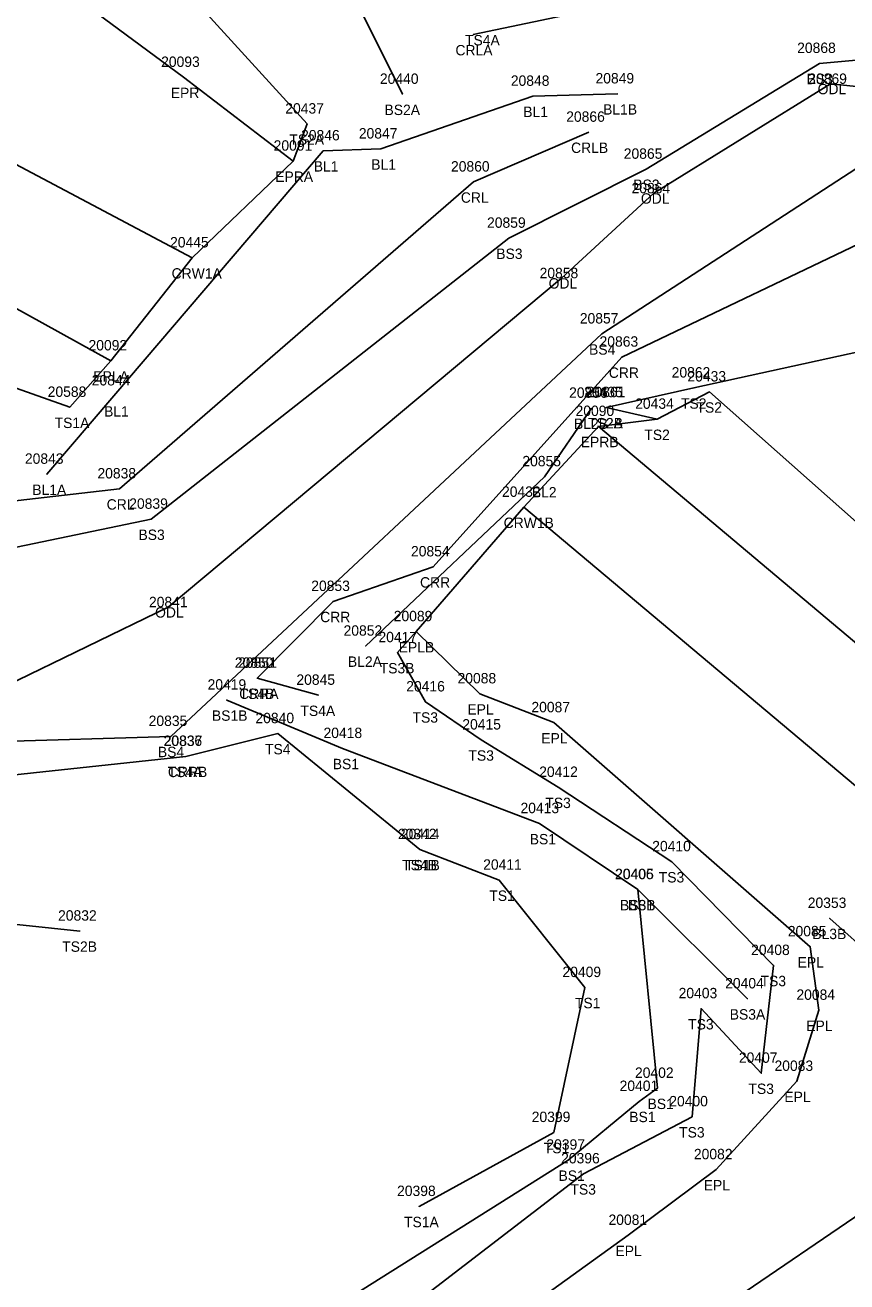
# Model space of a CAD drawing. Extents: x 1813127 to 1814107, y 1178171 to 1179078.
# Drawn here: x 1813724.7 to 1813803.8, y 1178619.3 to 1178740.3 of the extents above; entities that cross this region are included whole.
import ezdxf

# ---------------------------------------------------------------- set-up
doc = ezdxf.new("R2010")
doc.units = 0
for name, color, linetype in [('Default', 7, 'Continuous'), ('RD_DTM_BkLn1', 7, 'Continuous'), ('RD_DTM_BkLn2', 7, 'Continuous'), ('RD_EX_H2O', 7, 'Continuous'), ('RD_EX_H2O_txCode', 7, 'Continuous'), ('RD_EX_Road', 7, 'Continuous'), ('RD_EX_Road_txCode', 7, 'Continuous'), ('RD_SMD_Locator', 7, 'Continuous'), ('RD_SMD_Misc', 7, 'Continuous')]:
    doc.layers.add(name, color=color, linetype=linetype)

msp = doc.modelspace()

# ---------------------------------------------------------------- linework, layer by layer
at = {"layer": 'Default'}
msp.add_lwpolyline([(1813785.53, 1178702.33), (1813779.87, 1178701.64), (1813772.7, 1178693.86), (1813762.33, 1178681.89), (1813760.53, 1178679.87)], dxfattribs=at)
at = {"layer": 'RD_DTM_BkLn1'}
msp.add_line((1813820.26, 1178638.1), (1813802.14, 1178654.3), dxfattribs=at)
for points in [[(1813740.76, 1178717.86), (1813693.97, 1178742.65), (1813652.18, 1178753.85), (1813643.74, 1178755.64), (1813595, 1178763.51), (1813546.44, 1178770.61), (1813497.6, 1178777.62), (1813448.59, 1178785.89), (1813401.09, 1178795.04), (1813353.48, 1178806.76), (1813306.05, 1178819.85), (1813260.03, 1178834.12), (1813213.64, 1178849.47), (1813166.61, 1178866.29)], [(1813726.79, 1178697.04), (1813733.22, 1178704.58), (1813753.39, 1178728.16), (1813758.93, 1178728.34), (1813773.56, 1178733.41), (1813781.71, 1178733.64)], [(1813757.46, 1178680.5), (1813774.67, 1178696.8), (1813779.19, 1178703.39)], [(1814069.63, 1178419.56), (1814043.03, 1178443.95), (1814031.76, 1178453.98), (1813994.68, 1178489.07), (1813958.14, 1178523.5), (1813920.87, 1178558.86), (1813884.46, 1178593.47), (1813847.15, 1178628.98), (1813831.28, 1178643.33), (1813810.03, 1178662.5), (1813772.7, 1178693.86)], [(1813831.28, 1178643.33), (1813821.11, 1178637.41), (1813809.78, 1178629.12), (1813788.78, 1178614.79), (1813747.67, 1178586.85), (1813706.5, 1178558.14), (1813665.11, 1178528), (1813623.37, 1178496.83), (1813582.75, 1178466.66)]]:
    msp.add_lwpolyline(points, dxfattribs=at)
at = {"layer": 'RD_DTM_BkLn2'}
for p, q in [((1813752.92, 1178675.77), (1813747.03, 1178677.41)), ((1813794.23, 1178646.56), (1813783.65, 1178657.07))]:
    msp.add_line(p, q, dxfattribs=at)
for points in [[(1813751.85, 1178730.74), (1813741.17, 1178742.44), (1813717.67, 1178762.1), (1813698.84, 1178775.48), (1813689.15, 1178782.4), (1813688.55, 1178790.23), (1813686.56, 1178796.15), (1813687.57, 1178849.05), (1813684.25, 1178850.31), (1813686.08, 1178900.25), (1813688.49, 1178947.42), (1813691.04, 1178995.37), (1813694.64, 1179045.56)], [(1813761, 1178733.6), (1813755.04, 1178745.59), (1813738.22, 1178758.92), (1813720.3, 1178769.51), (1813690.62, 1178785.84)], [(1813728.98, 1178703.48), (1813680.74, 1178720.54), (1813670.9, 1178725.8), (1813665.35, 1178733.78), (1813654.36, 1178734.63), (1813647.32, 1178729.73), (1813639.1, 1178730.74), (1813591.11, 1178743.16), (1813543.28, 1178751.57), (1813511.7, 1178756.57), (1813494.92, 1178760.32), (1813445.74, 1178769.42), (1813422.91, 1178772.94), (1813422.78, 1178770.34)], [(1813501.61, 1178700.78), (1813535.62, 1178707.92), (1813578.65, 1178686.08), (1813588.2, 1178681.74), (1813622.61, 1178682.2), (1813653.79, 1178685.74), (1813685.17, 1178685.29), (1813723.1, 1178689.85), (1813736.83, 1178692.71), (1813771.26, 1178719.75), (1813784.46, 1178726.39), (1813801.14, 1178736.57), (1813819.08, 1178738.18), (1813840.25, 1178734.78), (1813848.44, 1178735.38), (1813862.15, 1178734.12), (1813885.61, 1178732.56), (1813903.34, 1178733.15)], [(1813751.85, 1178730.74), (1813750.48, 1178727.17), (1813740.76, 1178717.86)], [(1813494.55, 1178680.43), (1813533.86, 1178695.27), (1813573.03, 1178675.94), (1813630.33, 1178669.28), (1813656.92, 1178672.11), (1813691.39, 1178675.03), (1813721.31, 1178671.27), (1813738.7, 1178671.81), (1813780.2, 1178710.54), (1813805.93, 1178727.26), (1813819.91, 1178727.35), (1813841.4, 1178723.71), (1813860.66, 1178719.9), (1813869.89, 1178724.9), (1813872.35, 1178725.71), (1813884.47, 1178724.42), (1813903.61, 1178724.04)], [(1813740.76, 1178717.86), (1813732.94, 1178707.95), (1813728.98, 1178703.48)], [(1813780.61, 1178703.45), (1813789.06, 1178705.34), (1813820, 1178712.11), (1813829.02, 1178714.89)], [(1814080.77, 1178431.89), (1814053.55, 1178456.53), (1814053.55, 1178456.53), (1814043.11, 1178466.04), (1814008.23, 1178502.68), (1813981.17, 1178545.08), (1813940.17, 1178583.78), (1813898.27, 1178611.44), (1813860.48, 1178642.94), (1813824.26, 1178675.11), (1813790.56, 1178704.96), (1813785.53, 1178702.33), (1813780.61, 1178703.45)], [(1813648.32, 1178539.4), (1813697.26, 1178570.92), (1813738.71, 1178599.2), (1813778.43, 1178629.72), (1813788.89, 1178635.21), (1813789.75, 1178645.61), (1813795.55, 1178639.4), (1813796.73, 1178649.77), (1813786.93, 1178659.75), (1813776.01, 1178666.91), (1813768.6, 1178671.47), (1813763.23, 1178675.13), (1813760.53, 1178679.87)], [(1813647.13, 1178541.2), (1813695.54, 1178572.96), (1813738.1, 1178600.74), (1813742.95, 1178609.65), (1813776.97, 1178631.04), (1813783.78, 1178636.69), (1813785.55, 1178637.95), (1813783.65, 1178657.07), (1813774.21, 1178663.42), (1813755.25, 1178670.65), (1813744.09, 1178675.31)], [(1813740.16, 1178669.89), (1813749.02, 1178672.08), (1813762.69, 1178660.92)], [(1813623.26, 1178662.12), (1813655.04, 1178658.73), (1813668.37, 1178660.89), (1813682.02, 1178658.15), (1813729.97, 1178653.08)], [(1813762.61, 1178626.58), (1813775.57, 1178633.7), (1813778.57, 1178647.65), (1813770.33, 1178657.98), (1813762.69, 1178660.92)]]:
    msp.add_lwpolyline(points, dxfattribs=at)
at = {"layer": 'RD_EX_H2O'}
for points in [[(1813767.83, 1178739.34), (1813802.7, 1178746.65), (1813832.24, 1178749.11), (1813880.12, 1178745.59), (1813913.04, 1178737.89)], [(1813497.15, 1178691.5), (1813535.61, 1178703.5), (1813575.96, 1178680.52), (1813619.86, 1178677.62), (1813650.02, 1178676.71), (1813688.26, 1178680.15), (1813722.87, 1178676.67), (1813738.45, 1178684.24), (1813776.33, 1178715.9), (1813785.2, 1178724.07), (1813802.21, 1178734.6), (1813820.03, 1178732.78), (1813837.63, 1178729.78), (1813857.38, 1178730.32)], [(1813721.21, 1178694.19), (1813733.77, 1178695.63), (1813767.86, 1178725.16), (1813778.94, 1178729.95)], [(1813747.03, 1178677.41), (1813754.34, 1178684.8), (1813763.95, 1178688.13), (1813782.12, 1178708.31), (1813807.89, 1178720.63), (1813829.02, 1178714.89), (1813841.06, 1178713.13), (1813882.92, 1178708.73), (1813906.37, 1178716.29)], [(1813494.93, 1178677.14), (1813538.08, 1178685.02), (1813548.67, 1178684.4), (1813554.06, 1178674.83), (1813572.78, 1178667.8), (1813599.8, 1178663.18), (1813623.26, 1178662.12), (1813655.35, 1178662.6), (1813687.65, 1178668.53), (1813720.68, 1178667.78), (1813740.16, 1178669.89)]]:
    msp.add_lwpolyline(points, dxfattribs=at)
at = {"layer": 'RD_EX_Road'}
for points in [[(1813750.48, 1178727.17), (1813739.94, 1178735.23), (1813706.04, 1178760.25), (1813693.68, 1178773.78), (1813687.15, 1178785.68), (1813683.91, 1178796.53), (1813681.81, 1178824.01), (1813682.76, 1178849.48), (1813684.82, 1178900.28), (1813687.23, 1178946.66), (1813689.58, 1178995.92), (1813691.79, 1179045.45)], [(1813732.94, 1178707.95), (1813689.88, 1178731.75), (1813641.71, 1178744.36), (1813593.37, 1178752.09), (1813544.49, 1178758.77), (1813495.45, 1178766.29), (1813446.8, 1178774.66), (1813426.54, 1178777.95), (1813403.21, 1178782.55), (1813398.65, 1178783.84), (1813350.68, 1178796.09), (1813343.23, 1178797.92), (1813318.7, 1178804.23), (1813303.26, 1178808.85), (1813256.8, 1178823.17), (1813209.81, 1178838.91), (1813163.27, 1178855.57)], [(1814076.45, 1178427.4), (1814038.86, 1178461.87), (1814001.83, 1178496.62), (1813965.15, 1178531.54), (1813928.08, 1178567.1), (1813892.01, 1178601.23), (1813854.54, 1178636.51), (1813817.44, 1178670.03), (1813779.87, 1178701.64)], [(1813577.25, 1178474.27), (1813618.17, 1178504.26), (1813659.38, 1178535.26), (1813701.1, 1178565.69), (1813742.11, 1178594.54), (1813782.72, 1178623.8), (1813791.22, 1178630.12), (1813798.98, 1178638.62), (1813801.09, 1178645.46), (1813800.26, 1178651.57), (1813775.58, 1178673.13), (1813768.46, 1178675.91), (1813762.33, 1178681.89)]]:
    msp.add_lwpolyline(points, dxfattribs=at)
at = {"layer": 'RD_SMD_Locator'}
for centre in [(1813767.83, 1178739.34), (1813801.14, 1178736.57), (1813739.94, 1178735.23), (1813761, 1178733.6), (1813781.71, 1178733.64), (1813802.21, 1178734.6), (1813773.56, 1178733.41), (1813751.85, 1178730.74), (1813778.94, 1178729.95), (1813753.39, 1178728.16), (1813758.93, 1178728.34), (1813750.48, 1178727.17), (1813784.46, 1178726.39), (1813767.86, 1178725.16), (1813785.2, 1178724.07), (1813771.26, 1178719.75), (1813740.76, 1178717.86), (1813776.33, 1178715.9), (1813780.2, 1178710.54), (1813782.12, 1178708.31), (1813732.94, 1178707.95), (1813733.22, 1178704.58), (1813789.06, 1178705.34), (1813790.56, 1178704.96), (1813728.98, 1178703.48), (1813779.19, 1178703.39), (1813780.61, 1178703.45), (1813780.61, 1178703.45), (1813785.53, 1178702.33), (1813779.87, 1178701.64), (1813726.79, 1178697.04), (1813774.67, 1178696.8), (1813733.77, 1178695.63), (1813772.7, 1178693.86), (1813736.83, 1178692.71), (1813763.95, 1178688.13), (1813738.45, 1178684.24), (1813754.34, 1178684.8), (1813762.33, 1178681.89), (1813757.46, 1178680.5), (1813760.53, 1178679.87), (1813747.03, 1178677.41), (1813747.03, 1178677.41), (1813752.92, 1178675.77), (1813768.46, 1178675.91), (1813744.09, 1178675.31), (1813763.23, 1178675.13), (1813775.58, 1178673.13), (1813749.02, 1178672.08), (1813738.7, 1178671.81), (1813755.25, 1178670.65), (1813768.6, 1178671.47), (1813740.16, 1178669.89), (1813740.16, 1178669.89), (1813776.01, 1178666.91), (1813774.21, 1178663.42), (1813762.69, 1178660.92), (1813762.69, 1178660.92), (1813786.93, 1178659.75), (1813770.33, 1178657.98), (1813783.65, 1178657.07), (1813783.65, 1178657.07), (1813802.14, 1178654.3), (1813729.97, 1178653.08), (1813800.26, 1178651.57), (1813796.73, 1178649.77), (1813778.57, 1178647.65), (1813794.23, 1178646.56), (1813789.75, 1178645.61), (1813801.09, 1178645.46), (1813795.55, 1178639.4), (1813798.98, 1178638.62), (1813785.55, 1178637.95), (1813783.78, 1178636.69), (1813788.89, 1178635.21), (1813775.57, 1178633.7), (1813776.97, 1178631.04), (1813778.43, 1178629.72), (1813791.22, 1178630.12), (1813762.61, 1178626.58), (1813782.72, 1178623.8)]:
    msp.add_circle(centre, 0.001, dxfattribs=at)

# ---------------------------------------------------------------- texts
at = {"layer": 'RD_EX_H2O_txCode'}
for s, p in [('CRLA', (1813766.11, 1178737.34)), ('20869', (1813800.07, 1178734.6)), ('ODL', (1813800.97, 1178733.6)), ('20866', (1813776.77, 1178730.95)), ('CRLB', (1813777.24, 1178727.95)), ('20860', (1813765.68, 1178726.16)), ('20864', (1813783.06, 1178724.07)), ('CRL', (1813766.63, 1178723.16)), ('ODL', (1813783.96, 1178723.07)), ('20858', (1813774.21, 1178715.9)), ('ODL', (1813775.08, 1178714.9)), ('20863', (1813779.98, 1178709.31)), ('CRR', (1813780.87, 1178706.31)), ('20838', (1813731.65, 1178696.63)), ('CRL', (1813732.54, 1178693.63)), ('20854', (1813761.83, 1178689.13)), ('20853', (1813752.23, 1178685.8)), ('CRR', (1813762.7, 1178686.13)), ('20841', (1813736.61, 1178684.24)), ('ODL', (1813737.2, 1178683.24)), ('CRR', (1813753.09, 1178682.8)), ('20851', (1813745.2, 1178678.41)), ('CRRA', (1813745.29, 1178675.41)), ('20836', (1813738.01, 1178670.89)), ('CRRB', (1813738.43, 1178667.89))]:
    msp.add_text(s, height=1, dxfattribs=at).set_placement(p)
at = {"layer": 'RD_EX_Road_txCode'}
for s, p in [('20093', (1813737.78, 1178736.23)), ('EPR', (1813738.71, 1178733.23)), ('20091', (1813748.61, 1178728.17)), ('EPRA', (1813748.76, 1178725.17)), ('20092', (1813730.79, 1178708.95)), ('EPLA', (1813731.25, 1178705.95)), ('20090', (1813777.67, 1178702.64)), ('EPRB', (1813778.17, 1178699.64)), ('20089', (1813760.17, 1178682.89)), ('EPLB', (1813760.65, 1178679.89)), ('20088', (1813766.31, 1178676.91)), ('EPL', (1813767.26, 1178673.91)), ('20087', (1813773.42, 1178674.13)), ('EPL', (1813774.37, 1178671.13)), ('20085', (1813798.1, 1178652.57)), ('EPL', (1813799.05, 1178649.57)), ('20084', (1813798.93, 1178646.46)), ('EPL', (1813799.88, 1178643.46)), ('20083', (1813796.82, 1178639.62)), ('EPL', (1813797.77, 1178636.62)), ('20082', (1813789.06, 1178631.12)), ('EPL', (1813790.01, 1178628.12)), ('20081', (1813780.84, 1178624.8)), ('EPL', (1813781.51, 1178621.8))]:
    msp.add_text(s, height=1, dxfattribs=at).set_placement(p)
at = {"layer": 'RD_SMD_Misc'}
for s, p in [('TS4A', (1813767.03, 1178738.3)), ('20868', (1813799, 1178737.57)), ('20440', (1813758.84, 1178734.6)), ('20848', (1813771.44, 1178734.41)), ('20849', (1813779.59, 1178734.64)), ('BS3', (1813799.91, 1178734.57)), ('20437', (1813749.73, 1178731.74)), ('BS2A', (1813759.28, 1178731.6)), ('BL1', (1813772.64, 1178731.41)), ('BL1B', (1813780.32, 1178731.64)), ('20846', (1813751.25, 1178729.16)), ('20847', (1813756.81, 1178729.34)), ('TS2A', (1813750.12, 1178728.74)), ('20865', (1813782.31, 1178727.39)), ('BL1', (1813752.47, 1178726.16)), ('BL1', (1813758.01, 1178726.34)), ('BS3', (1813783.23, 1178724.39)), ('20859', (1813769.15, 1178720.75)), ('20445', (1813738.64, 1178718.86)), ('BS3', (1813770.04, 1178717.75)), ('CRW1A', (1813738.79, 1178715.86)), ('20857', (1813778.08, 1178711.54)), ('BS4', (1813778.97, 1178708.54)), ('20862', (1813786.92, 1178706.34)), ('20433', (1813788.44, 1178705.96)), ('20844', (1813731.1, 1178705.58)), ('20588', (1813726.86, 1178704.48)), ('20856', (1813777.05, 1178704.39)), ('20435', (1813778.49, 1178704.45)), ('20861', (1813778.75, 1178704.45)), ('BL1', (1813732.29, 1178702.58)), ('20434', (1813783.41, 1178703.33)), ('TS2', (1813787.82, 1178703.34)), ('TS2', (1813789.31, 1178702.96)), ('TS1A', (1813727.53, 1178701.48)), ('BL2B', (1813777.52, 1178701.39)), ('TS2A', (1813778.88, 1178701.45)), ('TS2B', (1813778.89, 1178701.45)), ('TS2', (1813784.29, 1178700.33)), ('20843', (1813724.67, 1178698.04)), ('20855', (1813772.55, 1178697.8)), ('BL1A', (1813725.38, 1178695.04)), ('20432', (1813770.59, 1178694.86)), ('BL2', (1813773.46, 1178694.8)), ('20839', (1813734.71, 1178693.71)), ('CRW1B', (1813770.75, 1178691.86)), ('BS3', (1813735.6, 1178690.71)), ('20852', (1813755.34, 1178681.5)), ('20417', (1813758.7, 1178680.87)), ('20850', (1813744.87, 1178678.41)), ('BL2A', (1813755.76, 1178678.5)), ('TS3B', (1813758.82, 1178677.87)), ('20419', (1813742.25, 1178676.31)), ('20845', (1813750.8, 1178676.77)), ('20416', (1813761.37, 1178676.13)), ('TS4B', (1813745.32, 1178675.41)), ('BS1B', (1813742.67, 1178673.31)), ('TS4A', (1813751.19, 1178673.77)), ('20835', (1813736.58, 1178672.81)), ('20840', (1813746.86, 1178673.08)), ('TS3', (1813761.98, 1178673.13)), ('20415', (1813766.77, 1178672.47)), ('20837', (1813738.04, 1178670.89)), ('20418', (1813753.41, 1178671.65)), ('BS4', (1813737.47, 1178669.81)), ('TS4', (1813747.78, 1178670.08)), ('BS1', (1813754.3, 1178668.65)), ('TS3', (1813767.36, 1178669.47)), ('TS4A', (1813738.42, 1178667.89)), ('20412', (1813774.17, 1178667.91)), ('TS3', (1813774.76, 1178664.91)), ('20413', (1813772.37, 1178664.42)), ('20842', (1813760.57, 1178661.92)), ('20414', (1813760.86, 1178661.92)), ('BS1', (1813773.26, 1178661.42)), ('20410', (1813785.05, 1178660.75)), ('TS4B', (1813760.98, 1178658.92)), ('TS1B', (1813761.26, 1178658.92)), ('20411', (1813768.78, 1178658.98)), ('20406', (1813781.46, 1178658.07)), ('20405', (1813781.49, 1178658.07)), ('TS3', (1813785.68, 1178657.75)), ('TS1', (1813769.37, 1178655.98)), ('20353', (1813800.02, 1178655.3)), ('20832', (1813727.86, 1178654.08)), ('BS3B', (1813781.95, 1178655.07)), ('BS1', (1813782.7, 1178655.07)), ('BL3B', (1813800.46, 1178652.3)), ('TS2B', (1813728.26, 1178651.08)), ('20408', (1813794.57, 1178650.77)), ('20409', (1813776.41, 1178648.65)), ('20404', (1813792.07, 1178647.56)), ('TS3', (1813795.48, 1178647.77)), ('TS1', (1813777.61, 1178645.65)), ('20403', (1813787.59, 1178646.61)), ('BS3A', (1813792.51, 1178644.56)), ('TS3', (1813788.51, 1178643.61)), ('20407', (1813793.39, 1178640.4)), ('20402', (1813783.39, 1178638.95)), ('20401', (1813781.91, 1178637.69)), ('TS3', (1813794.31, 1178637.4)), ('BS1', (1813784.6, 1178635.95)), ('20400', (1813786.69, 1178636.21)), ('20399', (1813773.45, 1178634.7)), ('BS1', (1813782.84, 1178634.69)), ('TS3', (1813787.64, 1178633.21)), ('TS1', (1813774.61, 1178631.7)), ('20397', (1813774.86, 1178632.04)), ('20396', (1813776.28, 1178630.72)), ('BS1', (1813776.03, 1178629.04)), ('20398', (1813760.49, 1178627.58)), ('TS3', (1813777.18, 1178627.72)), ('TS1A', (1813761.16, 1178624.58))]:
    msp.add_text(s, height=1, dxfattribs=at).set_placement(p)

doc.saveas('drawing.dxf')
